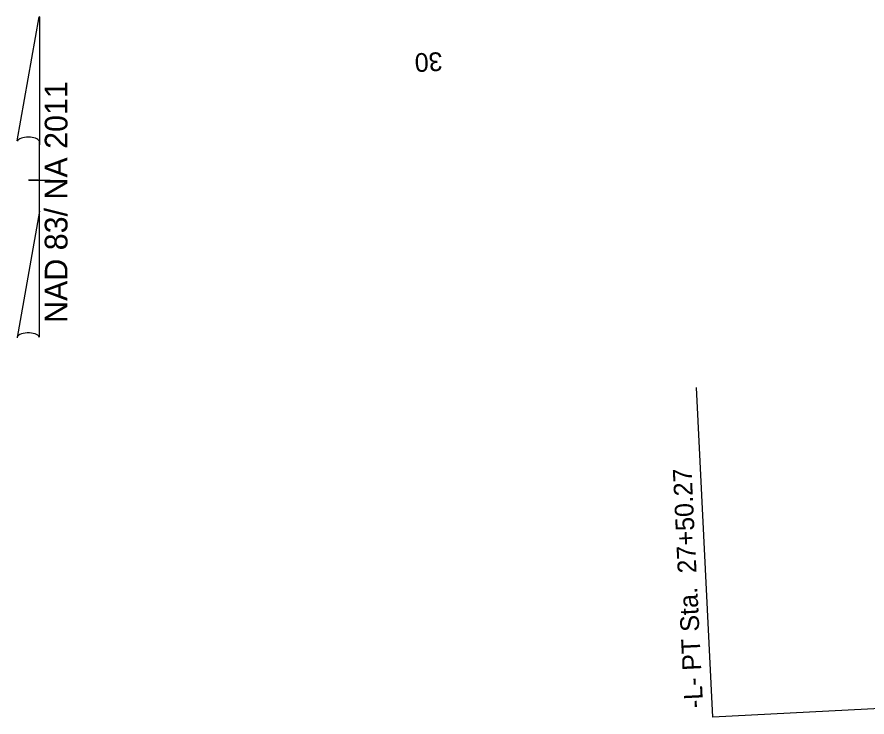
# Model space of a CAD drawing. Extents: x 2367848 to 2369479, y 800728 to 808616.
# Drawn here: x 2368407.2 to 2368725, y 803068.9 to 803330.6 of the extents above; entities that cross this region are included whole.
import ezdxf

# ---------------------------------------------------------------- set-up
doc = ezdxf.new("R2010")
doc.units = 0
for name, color, linetype in [('Prop Horizontal Alignment Station Label', 7, 'Continuous'), ('Prop Horizontal Alignment Tick Label', 7, 'Continuous'), ('Prop North Arrow NAD83 for Plan Sheets CELL', 7, 'Continuous')]:
    doc.layers.add(name, color=color, linetype=linetype)

msp = doc.modelspace()

# ---------------------------------------------------------------- linework, layer by layer
at = {"layer": 'Prop Horizontal Alignment Station Label'}
for p, q in [((2368667.28, 803068.9), (2368661.27, 803192.13)), ((2368869.22, 803079.04), (2368667.28, 803068.9))]:
    msp.add_line(p, q, dxfattribs=at)
at = {"layer": 'Prop North Arrow NAD83 for Plan Sheets CELL'}
for p, q in [((2368407.26, 803284.23), (2368415.46, 803330.58)), ((2368415.51, 803330.58), (2368415.46, 803330.58)), ((2368415.51, 803330.58), (2368415.46, 803330.58)), ((2368415.51, 803330.58), (2368415.51, 803282.78)), ((2368415.51, 803257.98), (2368415.51, 803284.18)), ((2368415.51, 803282.78), (2368415.51, 803284.13)), ((2368411.51, 803269.58), (2368411.46, 803269.58)), ((2368415.06, 803269.58), (2368411.51, 803269.58)), ((2368411.56, 803269.58), (2368419.56, 803269.58)), ((2368415.51, 803257.98), (2368407.16, 803210.73)), ((2368415.56, 803210.93), (2368415.51, 803257.98))]:
    msp.add_line(p, q, dxfattribs=at)
for centre, start_param, end_param in [((2368411.39, 803283.73), 0.216388, 2.908219), ((2368411.39, 803210.56), 0.201328, 3.141593)]:
    msp.add_ellipse(centre, major_axis=(4.23, -0.03), ratio=0.461098, start_param=start_param, end_param=end_param, dxfattribs=at)

# ---------------------------------------------------------------- texts
at = {"layer": 'Prop Horizontal Alignment Station Label'}
msp.add_text('-L- PT Sta.  27+50.27', height=7, rotation=92.7929, dxfattribs=at).set_placement((2368663.71, 803072.38))
at = {"layer": 'Prop Horizontal Alignment Tick Label'}
msp.add_text('30', height=7, rotation=182.8516, dxfattribs=at).set_placement((2368566.09, 803317.48))
at = {"layer": 'Prop North Arrow NAD83 for Plan Sheets CELL'}
msp.add_text('NAD 83/ NA 2011', height=8.5, rotation=90, dxfattribs=at).set_placement((2368426.03, 803216.22))

doc.saveas('drawing.dxf')
